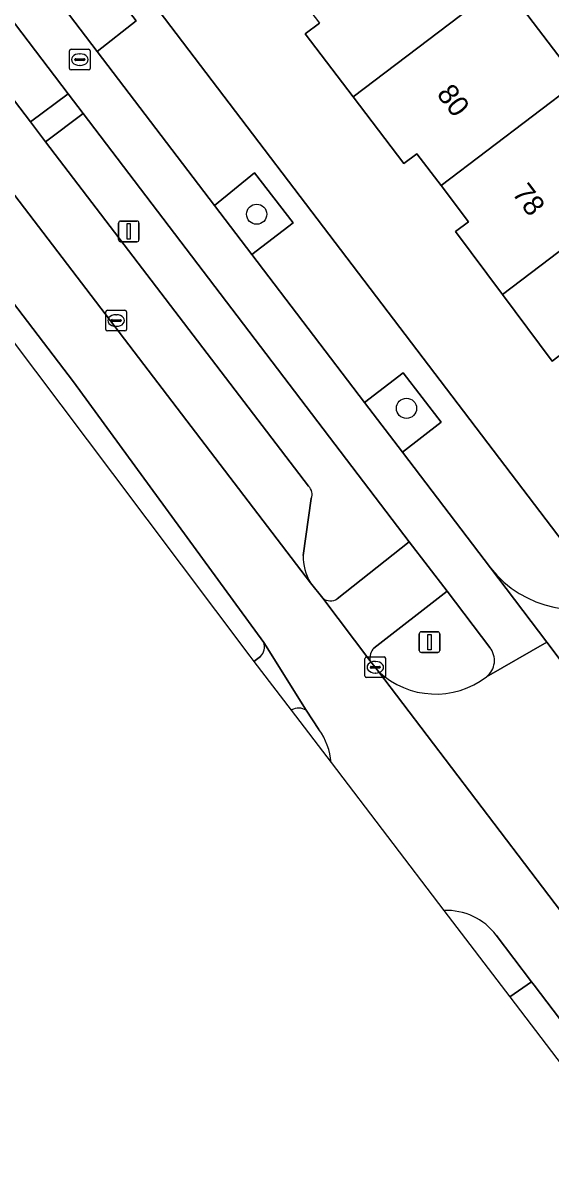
# Model space of a CAD drawing. Extents: x 160030 to 160839, y 385325 to 386450.
# Drawn here: x 160374.7 to 160400.3, y 385598.3 to 385654.3 of the extents above; entities that cross this region are included whole.
import ezdxf

# ---------------------------------------------------------------- set-up
doc = ezdxf.new("R2010")
doc.units = 0
for name, color, linetype in [('IMGEO_Berm_groen', 7, 'Continuous'), ('IMGEO_Boom', 7, 'Continuous'), ('IMGEO_Erf', 7, 'Continuous'), ('IMGEO_Fietspad_gesloten', 7, 'Continuous'), ('IMGEO_Kolk', 7, 'Continuous'), ('IMGEO_Lichtmast', 7, 'Continuous'), ('IMGEO_Pand', 7, 'Continuous'), ('IMGEO_Pand_nummerreeks', 7, 'Continuous'), ('IMGEO_Parkeervlak_open', 7, 'Continuous'), ('IMGEO_Rijbaan_lokaal_gesloten', 7, 'Continuous'), ('IMGEO_Rijbaan_lokaal_open', 7, 'Continuous'), ('IMGEO_Rioolput', 7, 'Continuous'), ('IMGEO_Verkeerseiland_groen', 7, 'Continuous'), ('IMGEO_Voetpad_open', 7, 'Continuous')]:
    doc.layers.add(name, color=color, linetype=linetype)

msp = doc.modelspace()

# ---------------------------------------------------------------- linework, layer by layer
at = {"layer": 'IMGEO_Berm_groen'}
for points in [[(160331.999, 385695.269), (160331.866, 385695.169), (160379.034, 385632.462), (160385.689, 385623.614), (160385.884, 385623.358)], [(160386.366, 385624.273), (160377.154, 385636.907), (160332.71, 385695.206)], [(160377.618, 385649.899), (160375.797, 385648.527), (160388.532, 385631.843)], [(160389.918, 385626.387), (160393.407, 385629.147), (160377.618, 385649.899)], [(160388.665, 385631.241), (160388.275, 385628.49)], [(160388.619, 385627.166), (160389.227, 385626.413)], [(160385.884, 385623.358), (160386.201, 385623.599)]]:
    msp.add_lwpolyline(points, dxfattribs=at)
for points in [[(160357.654, 385676.185), (160355.819, 385674.756), (160375.071, 385649.504), (160376.889, 385650.857)], [(160378.552, 385656.522), (160376.655, 385655.061), (160378.29, 385652.906), (160380.176, 385654.395)], [(160385.913, 385647.022), (160383.977, 385645.439), (160385.777, 385643.076), (160387.785, 385644.61)], [(160393.117, 385637.342), (160391.247, 385635.898), (160393.079, 385633.494), (160394.955, 385634.94)], [(160423.782, 385573.631), (160423.782, 385573.631), (160424.283, 385573.958), (160420.599, 385579.834), (160399.454, 385607.672), (160399.336, 385607.828), (160398.277, 385607.097)]]:
    msp.add_lwpolyline(points, close=True, dxfattribs=at)
for centre, radius, start, end in [((160388.149, 385631.443), 0.554, 338.6569, 46.2596), ((160390.839, 385628.45), 2.565, 179.0964, 210.0326), ((160389.59, 385626.877), 0.589, 231.9199, 303.7705), ((160385.744, 385624.068), 0.655, 314.2587, 18.2296)]:
    msp.add_arc(centre, radius, start, end, dxfattribs=at)
at = {"layer": 'IMGEO_Boom'}
for centre in [(160386.019, 385645.02), (160393.273, 385635.618)]:
    msp.add_circle(centre, 0.489, dxfattribs=at)
at = {"layer": 'IMGEO_Erf'}
for points in [[(160339.544, 385709.767), (160401.163, 385628.731)], [(160397.949, 385656.227), (160401.582, 385651.452), (160403.367, 385652.81), (160404.736, 385651.012), (160402.95, 385649.654), (160405.215, 385646.677), (160408.849, 385641.902), (160412.656, 385636.898), (160417.77, 385640.691), (160416.205, 385642.632), (160419.075, 385644.947), (160414.527, 385650.928), (160411.69, 385648.65), (160410.218, 385650.483), (160408.634, 385652.455), (160411.471, 385654.733)], [(160404.281, 385628.312), (160409.991, 385632.61), (160410.095, 385633.957), (160409.605, 385634.586), (160405.98, 385631.84), (160405.805, 385632.07), (160405.195, 385631.608), (160402.844, 385634.71), (160403.54, 385635.237), (160402.278, 385636.903), (160401.086, 385638.476), (160400.325, 385637.9), (160397.921, 385641.128), (160395.647, 385644.183), (160396.275, 385644.66), (160394.949, 385646.406), (160393.774, 385647.952), (160393.149, 385647.476), (160390.694, 385650.708), (160388.374, 385653.761), (160389.06, 385654.283)]]:
    msp.add_lwpolyline(points, dxfattribs=at)
at = {"layer": 'IMGEO_Fietspad_gesloten'}
for points in [[(160333.853, 385707.542), (160337.038, 385703.058), (160338.961, 385700.51), (160356.929, 385677.14), (160357.654, 385676.185), (160376.889, 385650.857), (160377.618, 385649.899), (160393.407, 385629.147), (160395.24, 385626.755), (160397.312, 385624.027)], [(160397.145, 385622.614), (160400.065, 385624.282), (160397.346, 385627.892), (160393.079, 385633.494), (160391.247, 385635.898), (160385.777, 385643.076), (160383.977, 385645.439), (160378.29, 385652.906), (160376.655, 385655.061), (160371.275, 385662.152), (160369.368, 385664.665), (160363.85, 385671.938), (160361.976, 385674.409), (160356.639, 385681.442), (160354.764, 385683.91), (160349.583, 385690.729), (160347.708, 385693.198), (160342.44, 385700.132), (160340.557, 385702.595), (160336.836, 385707.457)]]:
    msp.add_lwpolyline(points, dxfattribs=at)
msp.add_arc((160396.551, 385623.401), 0.985, 307.0408, 39.4783, dxfattribs=at)
at = {"layer": 'IMGEO_Kolk'}
for p, q in [((160378.713, 385639.443), (160378.713, 385640.295)), ((160378.788, 385640.369), (160379.64, 385640.369)), ((160379.201, 385640.149), (160379.226, 385640.149)), ((160379.714, 385640.295), (160379.714, 385639.443)), ((160378.972, 385639.863), (160378.972, 385639.875)), ((160379.41, 385639.826), (160379.012, 385639.826)), ((160379.015, 385639.912), (160379.413, 385639.912)), ((160379.224, 385639.589), (160379.199, 385639.589)), ((160379.456, 385639.875), (160379.456, 385639.863)), ((160379.64, 385639.369), (160378.788, 385639.369)), ((160391.265, 385622.647), (160391.265, 385623.499)), ((160391.34, 385623.573), (160392.192, 385623.573)), ((160391.753, 385623.353), (160391.778, 385623.353)), ((160392.266, 385623.499), (160392.266, 385622.647)), ((160391.524, 385623.067), (160391.524, 385623.079)), ((160391.962, 385623.03), (160391.564, 385623.03)), ((160391.567, 385623.116), (160391.965, 385623.116)), ((160391.776, 385622.793), (160391.751, 385622.793)), ((160392.008, 385623.079), (160392.008, 385623.067)), ((160392.192, 385622.573), (160391.34, 385622.573))]:
    msp.add_line(p, q, dxfattribs=at)
for points in [[(160378.713, 385639.443), (160378.713, 385640.295)], [(160378.788, 385640.369), (160379.64, 385640.369)], [(160379.714, 385640.295), (160379.714, 385639.443)], [(160379.64, 385639.369), (160378.788, 385639.369)], [(160391.265, 385622.647), (160391.265, 385623.499)], [(160391.34, 385623.573), (160392.192, 385623.573)], [(160392.266, 385623.499), (160392.266, 385622.647)], [(160392.192, 385622.573), (160391.34, 385622.573)]]:
    msp.add_lwpolyline(points, dxfattribs=at)
for centre, radius, start, end in [((160378.79, 385640.293), 0.0765, 91.552, 178.448), ((160378.79, 385640.293), 0.0765, 91.552, 178.448), ((160379.638, 385640.293), 0.0765, 1.552, 88.448), ((160379.638, 385640.293), 0.0765, 1.552, 88.448), ((160379.012, 385639.872), 0.0403, 85.8775, 175.7526), ((160379.009, 385639.862), 0.0366, 178.938, 274.7102), ((160379.413, 385639.869), 0.043, 264.8664, 352.4533), ((160379.417, 385639.874), 0.0386, 1.7309, 96.639), ((160378.79, 385639.445), 0.0765, 181.552, 268.448), ((160378.79, 385639.445), 0.0765, 181.552, 268.448), ((160379.638, 385639.445), 0.0765, 271.552, 358.448), ((160379.638, 385639.445), 0.0765, 271.552, 358.448), ((160391.342, 385623.497), 0.0765, 91.552, 178.448), ((160391.342, 385623.497), 0.0765, 91.552, 178.448), ((160392.19, 385623.497), 0.0765, 1.552, 88.448), ((160392.19, 385623.497), 0.0765, 1.552, 88.448), ((160391.564, 385623.076), 0.0403, 85.8775, 175.7526), ((160391.561, 385623.066), 0.0366, 178.938, 274.7102), ((160391.965, 385623.073), 0.043, 264.8664, 352.4533), ((160391.969, 385623.078), 0.0386, 1.7309, 96.639), ((160391.342, 385622.649), 0.0765, 181.552, 268.448), ((160391.342, 385622.649), 0.0765, 181.552, 268.448), ((160392.19, 385622.649), 0.0765, 271.552, 358.448), ((160392.19, 385622.649), 0.0765, 271.552, 358.448)]:
    msp.add_arc(centre, radius, start, end, dxfattribs=at)
for centre, major_axis, ratio, start_param, end_param in [((160379.2, 385639.869), (-0.387, 0.002), 0.722429, 4.712389, 7.853982), ((160379.225, 385639.869), (-0.39, 0.002), 0.717154, 1.570796, 4.712389), ((160391.752, 385623.073), (-0.387, 0.002), 0.722429, 4.712389, 7.853982), ((160391.777, 385623.073), (-0.39, 0.002), 0.717154, 1.570796, 4.712389)]:
    msp.add_ellipse(centre, major_axis=major_axis, ratio=ratio, start_param=start_param, end_param=end_param, dxfattribs=at)
at = {"layer": 'IMGEO_Lichtmast'}
for p, q in [((160379.33, 385643.79), (160379.33, 385644.59)), ((160379.33, 385644.59), (160379.33, 385643.79)), ((160379.43, 385644.69), (160380.22, 385644.69)), ((160380.22, 385644.69), (160379.43, 385644.69)), ((160380.32, 385644.59), (160380.32, 385643.79)), ((160380.32, 385643.79), (160380.32, 385644.59)), ((160380.22, 385643.69), (160379.43, 385643.69)), ((160379.43, 385643.69), (160380.22, 385643.69)), ((160393.896, 385623.889), (160393.896, 385624.689)), ((160393.896, 385624.689), (160393.896, 385623.889)), ((160393.996, 385624.789), (160394.786, 385624.789)), ((160394.786, 385624.789), (160393.996, 385624.789)), ((160394.886, 385624.689), (160394.886, 385623.889)), ((160394.886, 385623.889), (160394.886, 385624.689)), ((160394.786, 385623.789), (160393.996, 385623.789)), ((160393.996, 385623.789), (160394.786, 385623.789))]:
    msp.add_line(p, q, dxfattribs=at)
for points in [[(160379.75, 385644.565), (160379.9, 385644.565), (160379.9, 385643.815), (160379.75, 385643.815), (160379.75, 385644.565)], [(160394.316, 385624.664), (160394.466, 385624.664), (160394.466, 385623.914), (160394.316, 385623.914), (160394.316, 385624.664)]]:
    msp.add_lwpolyline(points, dxfattribs=at)
for centre, start, end in [((160379.43, 385644.59), 90, 180), ((160379.43, 385644.59), 90, 180), ((160380.22, 385644.59), 0, 90), ((160380.22, 385644.59), 360, 90), ((160379.43, 385643.79), 180, 270), ((160379.43, 385643.79), 180, 270), ((160380.22, 385643.79), 270, 0), ((160380.22, 385643.79), 270, 0), ((160393.996, 385624.689), 90, 180), ((160393.996, 385624.689), 90, 180), ((160394.786, 385624.689), 0, 90), ((160394.786, 385624.689), 360, 90), ((160393.996, 385623.889), 180, 270), ((160393.996, 385623.889), 180, 270), ((160394.786, 385623.889), 270, 0), ((160394.786, 385623.889), 270, 0)]:
    msp.add_arc(centre, 0.1, start, end, dxfattribs=at)
at = {"layer": 'IMGEO_Pand'}
for points in [[(160387.75, 385656.007), (160389.06, 385654.283), (160388.374, 385653.761), (160390.694, 385650.708), (160397.949, 385656.227), (160394.316, 385661.002)], [(160390.694, 385650.708), (160393.149, 385647.476), (160393.774, 385647.952), (160394.949, 385646.406), (160401.582, 385651.452), (160397.949, 385656.227)], [(160405.215, 385646.677), (160402.95, 385649.654), (160404.736, 385651.012), (160403.367, 385652.81), (160401.582, 385651.452), (160394.949, 385646.406), (160396.275, 385644.66), (160395.647, 385644.183), (160397.921, 385641.128)], [(160397.921, 385641.128), (160400.325, 385637.9), (160401.086, 385638.476), (160402.278, 385636.903), (160408.849, 385641.902), (160405.215, 385646.677)]]:
    msp.add_lwpolyline(points, close=True, dxfattribs=at)
at = {"layer": 'IMGEO_Parkeervlak_open'}
for points in [[(160339.622, 385691.384), (160388.619, 385627.166)], [(160388.532, 385631.843), (160375.797, 385648.527), (160375.071, 385649.504), (160355.819, 385674.756)], [(160388.275, 385628.49), (160388.665, 385631.241)]]:
    msp.add_lwpolyline(points, dxfattribs=at)
for centre, radius, start, end in [((160388.149, 385631.443), 0.554, 338.6569, 46.2596), ((160390.839, 385628.45), 2.565, 179.0964, 210.0326)]:
    msp.add_arc(centre, radius, start, end, dxfattribs=at)
at = {"layer": 'IMGEO_Rijbaan_lokaal_gesloten'}
for points in [[(160428.145, 385575.243), (160427.224, 385576.448), (160424.301, 385580.274), (160405.148, 385605.526), (160401.828, 385609.865), (160401.444, 385610.367), (160401.35, 385610.462), (160391.925, 385622.872), (160391.504, 385623.403), (160389.227, 385626.413), (160388.619, 385627.166), (160339.622, 385691.384), (160336.141, 385695.945), (160335.232, 385697.173), (160332.71, 385695.206), (160377.154, 385636.907), (160386.366, 385624.273), (160388.422, 385620.989), (160389.034, 385620.054)], [(160403.696, 385619.461), (160400.065, 385624.282), (160397.145, 385622.614)], [(160391.925, 385622.872), (160401.35, 385610.462), (160401.444, 385610.367)], [(160389.62, 385618.456), (160395.085, 385611.285)], [(160397.618, 385610.089), (160399.336, 385607.828), (160399.454, 385607.672), (160420.599, 385579.834), (160424.283, 385573.958), (160426.023, 385571.14)]]:
    msp.add_lwpolyline(points, dxfattribs=at)
for centre, radius, start, end in [((160394.686, 385625.79), 4.017, 226.5879, 307.7529), ((160386.577, 385618.247), 3.05, 3.9348, 36.342), ((160395.223, 385608.298), 2.991, 36.7984, 92.6513)]:
    msp.add_arc(centre, radius, start, end, dxfattribs=at)
at = {"layer": 'IMGEO_Rijbaan_lokaal_open'}
msp.add_lwpolyline([(160397.346, 385627.892), (160400.065, 385624.282), (160403.696, 385619.461), (160405.943, 385616.479)], dxfattribs=at)
msp.add_arc((160401.482, 385631.116), 5.244, 217.9348, 298.4237, dxfattribs=at)
at = {"layer": 'IMGEO_Rioolput'}
for p, q in [((160376.955, 385652.085), (160376.955, 385652.937)), ((160377.03, 385653.011), (160377.882, 385653.011)), ((160377.956, 385652.937), (160377.956, 385652.085)), ((160377.214, 385652.505), (160377.214, 385652.517)), ((160377.652, 385652.468), (160377.254, 385652.468)), ((160377.257, 385652.554), (160377.655, 385652.554)), ((160377.443, 385652.791), (160377.468, 385652.791)), ((160377.698, 385652.517), (160377.698, 385652.505)), ((160377.882, 385652.011), (160377.03, 385652.011)), ((160377.466, 385652.231), (160377.441, 385652.231))]:
    msp.add_line(p, q, dxfattribs=at)
for points in [[(160376.955, 385652.085), (160376.955, 385652.937)], [(160377.03, 385653.011), (160377.882, 385653.011)], [(160377.956, 385652.937), (160377.956, 385652.085)], [(160377.882, 385652.011), (160377.03, 385652.011)]]:
    msp.add_lwpolyline(points, dxfattribs=at)
for centre, radius, start, end in [((160377.032, 385652.935), 0.0765, 91.552, 178.448), ((160377.032, 385652.935), 0.0765, 91.552, 178.448), ((160377.88, 385652.935), 0.0765, 1.552, 88.448), ((160377.88, 385652.935), 0.0765, 1.552, 88.448), ((160377.254, 385652.514), 0.0403, 85.8775, 175.7526), ((160377.251, 385652.504), 0.0366, 178.938, 274.7102), ((160377.655, 385652.511), 0.043, 264.8664, 352.4533), ((160377.659, 385652.516), 0.0386, 1.7309, 96.639), ((160377.032, 385652.087), 0.0765, 181.552, 268.448), ((160377.032, 385652.087), 0.0765, 181.552, 268.448), ((160377.88, 385652.087), 0.0765, 271.552, 358.448), ((160377.88, 385652.087), 0.0765, 271.552, 358.448)]:
    msp.add_arc(centre, radius, start, end, dxfattribs=at)
for centre, major_axis, ratio, start_param, end_param in [((160377.442, 385652.511), (-0.387, 0.002), 0.722429, 4.712389, 7.853982), ((160377.467, 385652.511), (-0.39, 0.002), 0.717154, 1.570796, 4.712389)]:
    msp.add_ellipse(centre, major_axis=major_axis, ratio=ratio, start_param=start_param, end_param=end_param, dxfattribs=at)
at = {"layer": 'IMGEO_Verkeerseiland_groen'}
for points in [[(160397.312, 385624.027), (160395.24, 385626.755), (160391.7, 385624.005)], [(160391.504, 385623.403), (160391.925, 385622.872)], [(160387.71, 385621.003), (160387.69, 385620.988), (160389.62, 385618.456)], [(160389.034, 385620.054), (160388.422, 385620.989)], [(160395.085, 385611.285), (160398.277, 385607.097)], [(160398.277, 385607.097), (160399.336, 385607.828), (160397.618, 385610.089)]]:
    msp.add_lwpolyline(points, dxfattribs=at)
for centre, radius, start, end in [((160392.225, 385623.501), 0.728, 136.1928, 187.7386), ((160396.551, 385623.401), 0.985, 307.0408, 39.4783), ((160394.686, 385625.79), 4.017, 226.5879, 307.7529), ((160388.054, 385620.384), 0.708, 58.6897, 119.0574), ((160386.577, 385618.247), 3.05, 3.9348, 36.342), ((160395.223, 385608.298), 2.991, 36.7984, 92.6513)]:
    msp.add_arc(centre, radius, start, end, dxfattribs=at)
at = {"layer": 'IMGEO_Voetpad_open'}
for points in [[(160401.163, 385628.731), (160339.544, 385709.767)], [(160371.275, 385662.152), (160376.655, 385655.061), (160378.552, 385656.522), (160380.176, 385654.395), (160378.29, 385652.906), (160383.977, 385645.439), (160385.913, 385647.022), (160387.785, 385644.61), (160385.777, 385643.076), (160391.247, 385635.898), (160393.117, 385637.342), (160394.955, 385634.94), (160393.079, 385633.494), (160397.346, 385627.892)], [(160391.7, 385624.005), (160395.24, 385626.755), (160393.407, 385629.147), (160389.918, 385626.387)], [(160389.227, 385626.413), (160391.504, 385623.403)], [(160388.422, 385620.989), (160386.366, 385624.273)], [(160386.201, 385623.599), (160385.884, 385623.358), (160387.69, 385620.988)], [(160387.69, 385620.988), (160387.71, 385621.003)]]:
    msp.add_lwpolyline(points, dxfattribs=at)
msp.add_lwpolyline([(160375.797, 385648.527), (160377.618, 385649.899), (160376.889, 385650.857), (160375.071, 385649.504)], close=True, dxfattribs=at)
for centre, radius, start, end in [((160401.482, 385631.116), 5.244, 217.9348, 298.4237), ((160389.59, 385626.877), 0.589, 231.9199, 303.7705), ((160385.744, 385624.068), 0.655, 314.2587, 18.2296), ((160392.225, 385623.501), 0.728, 136.1928, 187.7386), ((160388.054, 385620.384), 0.708, 58.6897, 119.0574)]:
    msp.add_arc(centre, radius, start, end, dxfattribs=at)

# ---------------------------------------------------------------- texts
at = {"layer": 'IMGEO_Pand_nummerreeks'}
for s, rotation, p in [('80', 307.2538, (160394.701, 385650.834)), ('78', 307.2535, (160398.355, 385646.031))]:
    msp.add_text(s, height=1, rotation=rotation, dxfattribs=at).set_placement(p)

doc.saveas('drawing.dxf')
